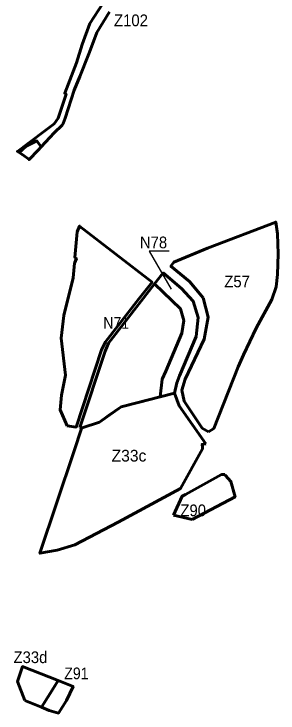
# Model space of a CAD drawing. Extents: x -650277 to -643420, y -1073980 to -1066720.
# Drawn here: x -648572 to -648031, y -1073980 to -1072548 of the extents above; entities that cross this region are included whole.
import ezdxf

# ---------------------------------------------------------------- set-up
doc = ezdxf.new("R2010")
doc.units = 0
doc.header["$LTSCALE"] = 9.6
for name, color, linetype, lineweight in [('24', 7, 'Continuous', 60), ('45', 7, 'Continuous', 60), ('48', 7, 'Continuous', 60), ('5', 7, 'Continuous', 60), ('60', 7, 'Continuous', 60), ('63', 7, 'Continuous', 25), ('9', 7, 'Continuous', 60)]:
    doc.layers.add(name, color=color, linetype=linetype, lineweight=lineweight)

msp = doc.modelspace()

# ---------------------------------------------------------------- linework, layer by layer
at = {"layer": '24'}
for points in [[(-648524.04, -1072809.71), (-648525.08, -1072808.24), (-648547.06, -1072818.59), (-648561.69, -1072831.54), (-648554.22, -1072836.89), (-648541.102, -1072846.281), (-648522.66, -1072826.92), (-648516.44, -1072820.39)], [(-648549.76, -1073954.86), (-648515.333, -1073968.584), (-648498, -1073940), (-648481.749, -1073913.76), (-648554.42, -1073885.092), (-648564.75, -1073915.91)]]:
    msp.add_lwpolyline(points, close=True, dxfattribs=at)
at = {"layer": '45'}
for points in [[(-648463.25, -1073392.125), (-648444.523, -1073394.235), (-648392.43, -1073235.98), (-648384.6, -1073219.54), (-648315.955, -1073131.889), (-648289.148, -1073097.66), (-648437.643, -1072982.601), (-648442.187, -1072994.5), (-648447.043, -1073046.967), (-648444.11, -1073048.69), (-648448.1, -1073058.393)], [(-648448.1, -1073058.393), (-648450.875, -1073088.375), (-648469.875, -1073165.5), (-648475.437, -1073212.375), (-648466.687, -1073288.25), (-648474.5, -1073328.75), (-648477.562, -1073358.875), (-648463.25, -1073392.125)], [(-648272.642, -1073332.558), (-648268, -1073296), (-648261, -1073280), (-648228, -1073202), (-648224, -1073176), (-648231, -1073152), (-648283.884, -1073101.15), (-648311.798, -1073137.127), (-648378.17, -1073222.67), (-648385.09, -1073238.58), (-648436.857, -1073395.099)], [(-648397.062, -1073384.375), (-648378.125, -1073370.875), (-648352.312, -1073353), (-648314.687, -1073343.25), (-648272.642, -1073332.558)], [(-648436.857, -1073395.099), (-648432.187, -1073395.625), (-648397.062, -1073384.375)]]:
    msp.add_lwpolyline(points, dxfattribs=at)
at = {"layer": '48'}
msp.add_lwpolyline([(-648231, -1073152), (-648224, -1073176), (-648228, -1073202), (-648261, -1073280), (-648268, -1073296), (-648272.642, -1073332.558), (-648243.08, -1073325.04), (-648237.98, -1073303.4), (-648232.64, -1073289.31), (-648198.7, -1073209.08), (-648194.2, -1073170.13), (-648205.04, -1073136.07), (-648228.91, -1073110.54), (-648266.38, -1073078.59), (-648283.884, -1073101.15)], close=True, dxfattribs=at)
at = {"layer": '5'}
for points in [[(-648272.642, -1073332.558), (-648352.312, -1073353), (-648397.062, -1073384.375)], [(-648179.07, -1073428.81), (-648233.36, -1073350.68), (-648243.08, -1073325.04), (-648272.642, -1073332.558)], [(-648397.062, -1073384.375), (-648432.187, -1073395.625), (-648433.206, -1073395.51), (-648449.599, -1073445.278)], [(-648447.06, -1073635.39), (-648358.69, -1073589.35), (-648230.81, -1073520.18), (-648185.34, -1073438.91), (-648185.82, -1073435.12), (-648186.46, -1073430.01), (-648183.46, -1073429.52), (-648179.07, -1073428.81)], [(-648449.599, -1073445.278), (-648518.867, -1073652.836), (-648483.58, -1073646.7), (-648447.06, -1073635.39), (-648447.06, -1073635.39)]]:
    msp.add_lwpolyline(points, dxfattribs=at)
at = {"layer": '60'}
msp.add_line((-648245.341, -1073575.152), (-648207, -1073584), dxfattribs=at)
for points in [[(-648389.69, -1072526.36), (-648416.41, -1072567.43), (-648432.45, -1072610.56), (-648443.77, -1072648.02), (-648468.01, -1072710.44), (-648465.25, -1072712.03), (-648478.58, -1072753.49), (-648481.62, -1072761.39), (-648489.76, -1072772.74), (-648506.1, -1072785.56), (-648542.43, -1072812.6), (-648564.86, -1072829.45), (-648561.69, -1072831.54), (-648547.06, -1072818.59), (-648525.08, -1072808.24), (-648524.04, -1072809.71), (-648516.44, -1072820.39), (-648489.69, -1072791.37), (-648473.13, -1072775.58), (-648470.89, -1072772.42), (-648467.286, -1072761.426), (-648448.58, -1072704.37), (-648436.75, -1072675.79), (-648418.45, -1072629.91), (-648409.08, -1072604.25), (-648401.91, -1072586.1), (-648376.47, -1072543.52)], [(-648139.56, -1073491.4), (-648146.4, -1073491.55), (-648220.42, -1073532.43), (-648227.63, -1073535.89), (-648245.341, -1073575.152)], [(-648207, -1073584), (-648119, -1073537), (-648127.31, -1073505.75), (-648138.41, -1073493.62), (-648139.56, -1073491.4)]]:
    msp.add_lwpolyline(points, dxfattribs=at)
msp.add_lwpolyline([(-648515.333, -1073968.584), (-648499.84, -1073974.76), (-648480.86, -1073980.25), (-648464.44, -1073954.69), (-648451.05, -1073925.87), (-648471, -1073918), (-648481.749, -1073913.76)], close=True, dxfattribs=at)
at = {"layer": '63'}
msp.add_lwpolyline([(-648254, -1073034), (-648295, -1073034), (-648250, -1073112)], dxfattribs=at)
at = {"layer": '9'}
for points in [[(-648030.86, -1073039.71), (-648032.09, -1072998.65), (-648035.592, -1072974.222), (-648175.061, -1073027.551), (-648244.214, -1073056.657), (-648250.491, -1073064.698), (-648212.22, -1073096.39), (-648184.37, -1073129.89)], [(-648101.67, -1073246.63), (-648075.34, -1073191.93), (-648043.29, -1073132.97), (-648034.43, -1073107.07), (-648031.8, -1073082.07), (-648030.86, -1073039.71)], [(-648184.37, -1073129.89), (-648174.03, -1073168.94), (-648182.12, -1073214.56), (-648221.39, -1073296.24), (-648227.75, -1073318.75), (-648223.03, -1073341.59), (-648186.47, -1073396.47), (-648173.38, -1073404.03)], [(-648173.38, -1073404.03), (-648162.55, -1073397.4), (-648112.36, -1073270.87), (-648101.67, -1073246.63)]]:
    msp.add_lwpolyline(points, dxfattribs=at)

# ---------------------------------------------------------------- texts
at = {"layer": '63'}
for s, width, p in [('Z102', 0.95, (-648367, -1072573)), ('N78', 0.95, (-648314, -1073028)), ('Z57', 0.95, (-648141, -1073108)), ('N71', 0.9, (-648389, -1073193)), ('Z90', 0.95, (-648231, -1073577)), ('Z33d', 0.95, (-648573, -1073878)), ('Z91', 0.9, (-648469, -1073911))]:
    msp.add_text(s, height=24, dxfattribs=dict(at, width=width)).set_placement(p)
msp.add_text('Z33c', height=24, dxfattribs=at).set_placement((-648372, -1073465))

doc.saveas('drawing.dxf')
